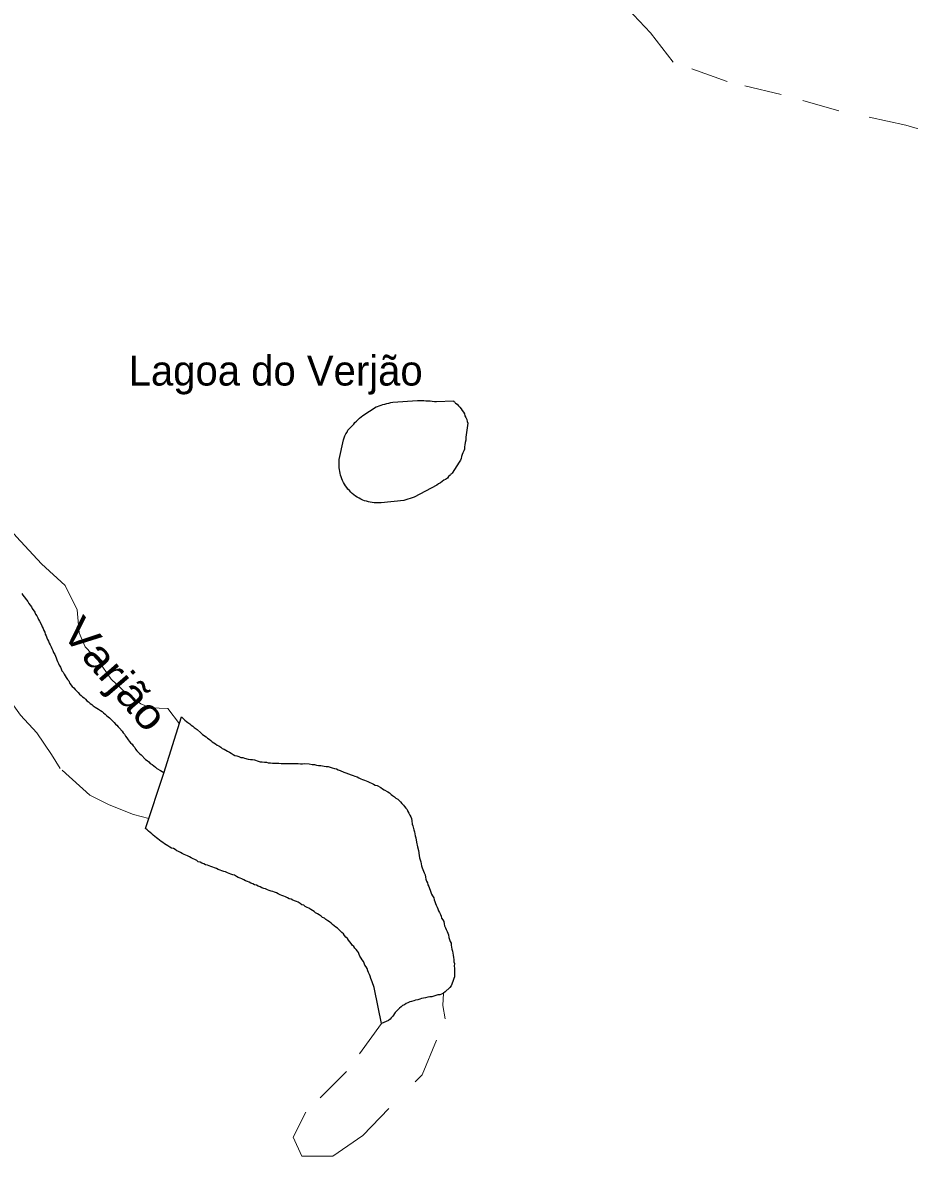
# Model space of a CAD drawing. Extents: x 785.9 to 812.4, y 7674.9 to 7703.1.
# Drawn here: x 791.218 to 793.585, y 7684.501 to 7687.529 of the extents above; entities that cross this region are included whole.
import ezdxf
from ezdxf.enums import TextEntityAlignment as Align

# ---------------------------------------------------------------- set-up
doc = ezdxf.new("R2010")
doc.units = 0
doc.header["$LTSCALE"] = 0.04
doc.linetypes.add('LONG_DASHED', pattern=[7.5, 6, -1.5])
doc.linetypes.add('SHORT_DASHED', pattern=[2.7, 1.5, -1.2])
for name, color, linetype, lineweight in [('2', 7, 'Continuous', 25), ('21', 7, 'SHORT_DASHED', 13), ('3', 7, 'LONG_DASHED', 25), ('7', 7, 'Continuous', 25)]:
    doc.layers.add(name, color=color, linetype=linetype, lineweight=lineweight)
doc.layers.add('61', color=7, linetype='Continuous')

msp = doc.modelspace()

# ---------------------------------------------------------------- linework, layer by layer
at = {"layer": '2'}
for points in [[(791.5945, 7685.5239), (791.5945, 7685.5239), (791.6422, 7685.6742)], [(791.6422, 7685.6742), (791.6439, 7685.6728), (791.6471, 7685.6688), (791.6512, 7685.6655), (791.6552, 7685.6623), (791.6592, 7685.6591), (791.6641, 7685.6558), (791.6681, 7685.6526), (791.6722, 7685.6494), (791.6762, 7685.6461), (791.6841, 7685.6408), (791.694, 7685.6315), (791.6981, 7685.6275), (791.7078, 7685.621)], [(791.7078, 7685.621), (791.7118, 7685.6178), (791.7159, 7685.6146), (791.7199, 7685.6113), (791.724, 7685.6081), (791.728, 7685.6048), (791.7329, 7685.6024), (791.7369, 7685.5992), (791.7418, 7685.5968), (791.7466, 7685.5935), (791.7507, 7685.5903), (791.7555, 7685.5879), (791.7604, 7685.5854), (791.7652, 7685.583), (791.7701, 7685.5798), (791.775, 7685.5773), (791.7798, 7685.5741), (791.7847, 7685.5717), (791.7895, 7685.5701), (791.7952, 7685.5684), (791.8, 7685.566), (791.8057, 7685.566), (791.8106, 7685.5644), (791.8203, 7685.5612), (791.8259, 7685.5603), (791.8316, 7685.5603), (791.8373, 7685.5595), (791.847, 7685.5563), (791.8518, 7685.5547), (791.8575, 7685.5547), (791.8632, 7685.5531), (791.8688, 7685.5531), (791.8737, 7685.5514), (791.8793, 7685.5514), (791.885, 7685.5506), (791.902, 7685.5506), (791.9077, 7685.5498), (791.9538, 7685.5498), (791.9594, 7685.549), (791.9651, 7685.549), (791.9708, 7685.5498), (791.9829, 7685.549), (791.991, 7685.5474), (791.9967, 7685.5474), (792.0023, 7685.5458), (792.008, 7685.545), (792.0137, 7685.5442), (792.0226, 7685.5425), (792.0282, 7685.5417), (792.0339, 7685.5417), (792.0387, 7685.5401), (792.0444, 7685.5385), (792.0509, 7685.5369), (792.0557, 7685.5353), (792.0606, 7685.5328), (792.0654, 7685.5312), (792.0751, 7685.5264), (792.0808, 7685.5247), (792.0954, 7685.5199), (792.1002, 7685.5175), (792.1051, 7685.5158), (792.1107, 7685.5142), (792.1156, 7685.5118), (792.1205, 7685.5086), (792.1253, 7685.5069), (792.1302, 7685.5053), (792.135, 7685.5037), (792.1399, 7685.5021), (792.1544, 7685.4948), (792.1593, 7685.4924), (792.1642, 7685.4908), (792.1739, 7685.4859), (792.1787, 7685.4827), (792.1828, 7685.4794), (792.1925, 7685.4746), (792.1973, 7685.4713), (792.2014, 7685.4673), (792.2054, 7685.4641), (792.2103, 7685.4608), (792.2143, 7685.4576), (792.2192, 7685.4543), (792.2232, 7685.4511), (792.2265, 7685.4471), (792.2305, 7685.443), (792.2345, 7685.439), (792.2378, 7685.4349), (792.241, 7685.4309), (792.2443, 7685.4268), (792.2467, 7685.422), (792.2491, 7685.4171), (792.2515, 7685.4123), (792.254, 7685.4074), (792.2564, 7685.4026), (792.2572, 7685.3969), (792.258, 7685.388), (792.2596, 7685.3831), (792.2621, 7685.3726), (792.2637, 7685.3678), (792.2653, 7685.3621), (792.2661, 7685.3564), (792.2677, 7685.3516)], [(791.546, 7685.3759), (791.5945, 7685.5239), (791.5945, 7685.5239)], [(791.7596, 7685.2602), (791.7547, 7685.2618), (791.7499, 7685.2634), (791.745, 7685.265), (791.7402, 7685.2666), (791.7353, 7685.2691), (791.7305, 7685.2715), (791.7256, 7685.2731), (791.7207, 7685.2747), (791.7159, 7685.2763), (791.711, 7685.278), (791.7062, 7685.2796), (791.7013, 7685.282), (791.6965, 7685.2836), (791.6916, 7685.286), (791.6868, 7685.2877), (791.6827, 7685.2909), (791.6779, 7685.2933), (791.673, 7685.2949), (791.6681, 7685.2982), (791.6633, 7685.3006), (791.6584, 7685.303), (791.6536, 7685.3055), (791.6487, 7685.3071), (791.6439, 7685.3095), (791.639, 7685.3119), (791.6342, 7685.3152), (791.6293, 7685.3168), (791.6253, 7685.32), (791.6204, 7685.3225), (791.6156, 7685.3241), (791.6107, 7685.3265), (791.6058, 7685.3297), (791.601, 7685.333), (791.5961, 7685.3354), (791.5921, 7685.3386), (791.5872, 7685.3419), (791.5832, 7685.3451), (791.5791, 7685.3483), (791.5751, 7685.3516), (791.5711, 7685.3548), (791.5662, 7685.3581), (791.563, 7685.3621), (791.5581, 7685.3653), (791.5541, 7685.3694), (791.55, 7685.3726), (791.546, 7685.3759)], [(792.2677, 7685.3516), (792.2693, 7685.3394), (792.2718, 7685.3273), (792.275, 7685.3176), (792.2766, 7685.3038), (792.2774, 7685.2982), (792.2791, 7685.2925), (792.2807, 7685.2869), (792.2823, 7685.282), (792.2831, 7685.2763), (792.2847, 7685.2715), (792.288, 7685.2626), (792.2896, 7685.2577), (792.2928, 7685.2529), (792.2936, 7685.2464), (792.2944, 7685.2407), (792.296, 7685.2359), (792.2985, 7685.231), (792.3001, 7685.2262), (792.3025, 7685.2213), (792.3041, 7685.2165), (792.3058, 7685.2116), (792.3074, 7685.2059), (792.3098, 7685.2011), (792.3122, 7685.1962), (792.3155, 7685.1914), (792.3163, 7685.1857), (792.3187, 7685.1809), (792.3203, 7685.176), (792.3219, 7685.1711), (792.3244, 7685.1663), (792.326, 7685.1614), (792.3284, 7685.1566), (792.3308, 7685.1517), (792.3333, 7685.1469), (792.3349, 7685.142), (792.3365, 7685.1372), (792.3397, 7685.1323), (792.3422, 7685.1275), (792.343, 7685.1218), (792.3446, 7685.1161), (792.347, 7685.1113), (792.3486, 7685.1064), (792.3511, 7685.1016), (792.3527, 7685.0967), (792.3551, 7685.0919), (792.3559, 7685.0854), (792.3575, 7685.0797), (792.3592, 7685.0749), (792.3616, 7685.07), (792.3616, 7685.0643), (792.3632, 7685.0595), (792.364, 7685.0538), (792.3656, 7685.049), (792.3664, 7685.0433), (792.3672, 7685.0376), (792.3681, 7685.032), (792.3689, 7685.0263), (792.3689, 7685.0206), (792.3705, 7685.0158), (792.3697, 7685.0085), (792.3713, 7685.0037), (792.3713, 7684.9859), (792.3705, 7684.9802), (792.3689, 7684.9753), (792.3672, 7684.9705), (792.364, 7684.9608), (792.3616, 7684.9559), (792.3583, 7684.9519), (792.3462, 7684.9397), (792.3414, 7684.9365), (792.3365, 7684.9341), (792.3316, 7684.9324), (792.326, 7684.9316), (792.3211, 7684.93), (792.3155, 7684.9284), (792.3106, 7684.9268), (792.3049, 7684.9268), (792.2993, 7684.926), (792.2936, 7684.9244), (792.288, 7684.9235), (792.2831, 7684.9219), (792.2782, 7684.9203), (792.2726, 7684.9187), (792.2669, 7684.9179), (792.2621, 7684.9163), (792.2564, 7684.9146), (792.2515, 7684.913), (792.2467, 7684.9106), (792.2418, 7684.909), (792.237, 7684.9057), (792.2321, 7684.9033), (792.2281, 7684.9001), (792.224, 7684.8968), (792.2159, 7684.8888), (792.2127, 7684.8847), (792.2062, 7684.875), (792.2022, 7684.871), (792.1989, 7684.8669), (792.1949, 7684.8637), (792.1763, 7684.8556)], [(792.1763, 7684.8556), (792.1577, 7684.947), (792.1561, 7684.9519), (792.1544, 7684.9567), (792.1528, 7684.9616), (792.1512, 7684.9664), (792.1496, 7684.9713), (792.1472, 7684.9761), (792.1455, 7684.9818), (792.1439, 7684.9867), (792.1415, 7684.9915), (792.1391, 7684.9964), (792.1375, 7685.002), (792.135, 7685.0069), (792.1318, 7685.0117), (792.1294, 7685.0166), (792.1277, 7685.0215), (792.1245, 7685.0255), (792.1213, 7685.0304), (792.118, 7685.0352), (792.1164, 7685.0401), (792.1148, 7685.0449), (792.1116, 7685.049), (792.1083, 7685.053), (792.1051, 7685.0571), (792.1018, 7685.0611), (792.0978, 7685.0651), (792.0946, 7685.0692), (792.0913, 7685.074), (792.0881, 7685.0781), (792.0849, 7685.0821), (792.0808, 7685.0862), (792.0776, 7685.0902), (792.0743, 7685.0951), (792.0703, 7685.0983), (792.0662, 7685.1024), (792.0622, 7685.1064), (792.0582, 7685.1097), (792.0541, 7685.1129), (792.0493, 7685.1161), (792.0452, 7685.1202), (792.0412, 7685.1234), (792.0371, 7685.1266), (792.0323, 7685.1299), (792.0274, 7685.1331), (792.0234, 7685.1364), (792.0185, 7685.1388), (792.0145, 7685.142), (792.0096, 7685.1453), (792.0048, 7685.1485), (791.9999, 7685.1509), (791.9959, 7685.1542), (791.9918, 7685.1574), (791.987, 7685.1598), (791.9821, 7685.1631), (791.9772, 7685.1655), (791.9724, 7685.1679), (791.9683, 7685.1711), (791.9635, 7685.1728), (791.9586, 7685.176), (791.9538, 7685.1792), (791.9489, 7685.1809), (791.9441, 7685.1833), (791.9392, 7685.1849), (791.9344, 7685.1873), (791.9295, 7685.1889), (791.9246, 7685.1914), (791.9198, 7685.1938), (791.9149, 7685.1954), (791.9101, 7685.1978), (791.9052, 7685.1995), (791.9004, 7685.2019), (791.8955, 7685.2043), (791.8907, 7685.2059), (791.8858, 7685.2076), (791.881, 7685.2092), (791.8761, 7685.2108), (791.8712, 7685.2124), (791.8664, 7685.2148), (791.8615, 7685.2165), (791.8567, 7685.2181), (791.8518, 7685.2205), (791.847, 7685.2221), (791.8421, 7685.2246), (791.8373, 7685.2262), (791.8324, 7685.2286), (791.8275, 7685.2302), (791.8227, 7685.2326), (791.8178, 7685.2351), (791.813, 7685.2367), (791.8081, 7685.2391), (791.8033, 7685.2415), (791.7984, 7685.244), (791.7936, 7685.2456), (791.7887, 7685.248), (791.7839, 7685.2513), (791.779, 7685.2529), (791.7741, 7685.2545), (791.7693, 7685.2561), (791.7644, 7685.2577), (791.7596, 7685.2602)]]:
    msp.add_lwpolyline(points, dxfattribs=at)
at = {"layer": '21'}
for points in [[(793.6703, 7687.2275), (793.576, 7687.2548), (793.397, 7687.2933), (793.2432, 7687.3366), (793.0987, 7687.3718), (792.9549, 7687.4236), (792.8941, 7687.5014), (792.834, 7687.5659)], [(791.5548, 7685.4027), (791.5139, 7685.4139), (791.4488, 7685.4396), (791.397, 7685.465), (791.3183, 7685.5366), (791.2948, 7685.574), (791.2556, 7685.6319), (791.212, 7685.6791), (791.1291, 7685.794), (791.1138, 7685.8382), (791.0887, 7685.9067), (791.0547, 7685.9514), (791.0527, 7686.0036), (790.9867, 7686.1088), (790.9293, 7686.1623), (790.874, 7686.207), (790.7932, 7686.2644), (790.621, 7686.3261), (790.6043, 7686.3329)], [(791.023, 7686.3275), (791.0544, 7686.3064), (791.0817, 7686.2797), (791.1387, 7686.2265), (791.2014, 7686.1556), (791.2682, 7686.083), (791.331, 7686.0251), (791.3636, 7685.9607), (791.3689, 7685.8993), (791.3844, 7685.8618), (791.4195, 7685.8251), (791.4545, 7685.7754), (791.4953, 7685.7371), (791.5336, 7685.7094), (791.5588, 7685.6988), (791.6053, 7685.6971), (791.6364, 7685.6559)], [(792.1763, 7684.8556), (792.0826, 7684.7274), (791.974, 7684.6187), (791.9405, 7684.5517), (791.9633, 7684.5007), (792.0463, 7684.5014), (792.1259, 7684.5566), (792.2843, 7684.7188), (792.3462, 7684.8677), (792.3394, 7684.9035), (792.3419, 7684.9368)]]:
    msp.add_lwpolyline(points, dxfattribs=at)
at = {"layer": '3'}
for points in [[(792.0722, 7686.3056), (792.0702, 7686.3104), (792.0684, 7686.3153), (792.0669, 7686.3202), (792.0656, 7686.3251), (792.0647, 7686.3299), (792.0639, 7686.3348), (792.0634, 7686.3395), (792.0631, 7686.3442), (792.063, 7686.3452), (792.063, 7686.3509), (792.063, 7686.3565), (792.063, 7686.3622), (792.0742, 7686.4144), (792.0743, 7686.4148), (792.0784, 7686.4253), (792.0808, 7686.4302), (792.084, 7686.435), (792.0865, 7686.4399), (792.0897, 7686.4439), (792.0938, 7686.448), (792.0978, 7686.452), (792.1018, 7686.4561), (792.1051, 7686.4609), (792.1091, 7686.4642), (792.1132, 7686.4682), (792.1172, 7686.4722), (792.1221, 7686.4755), (792.1261, 7686.4795), (792.1617, 7686.503), (792.165, 7686.5038), (792.1698, 7686.5054), (792.1747, 7686.507), (792.1795, 7686.5087), (792.1852, 7686.5095), (792.19, 7686.5111), (792.1957, 7686.5127), (792.2006, 7686.5143), (792.2062, 7686.5151), (792.2718, 7686.5192), (792.2774, 7686.5192), (792.2831, 7686.5192), (792.2888, 7686.5192), (792.2944, 7686.5184), (792.3001, 7686.5184), (792.3058, 7686.5184), (792.3114, 7686.5176), (792.3171, 7686.5168), (792.3227, 7686.5168), (792.368, 7686.5184), (792.3683, 7686.5181), (792.3695, 7686.5169), (792.3706, 7686.5158), (792.3718, 7686.5147), (792.3729, 7686.5135), (792.3737, 7686.5127), (792.3778, 7686.5095), (792.3818, 7686.5054), (792.385, 7686.5014), (792.3883, 7686.4973), (792.3915, 7686.4925), (792.3948, 7686.4884), (792.3972, 7686.4836), (792.3988, 7686.4787), (792.4012, 7686.4739), (792.4037, 7686.469), (792.4045, 7686.4633), (792.4061, 7686.4585), (792.4012, 7686.4213), (792.4012, 7686.4205), (792.4012, 7686.4188), (792.4012, 7686.4172), (792.4012, 7686.4156), (792.4012, 7686.414), (792.4012, 7686.4132), (792.3996, 7686.4075), (792.3988, 7686.401), (792.398, 7686.3954), (792.3972, 7686.3897), (792.3956, 7686.3849), (792.3931, 7686.38), (792.3915, 7686.3752), (792.3899, 7686.3695), (792.3883, 7686.3646), (792.3867, 7686.3598), (792.3834, 7686.3549), (792.3643, 7686.3253), (792.3637, 7686.3247), (792.3626, 7686.3236), (792.3614, 7686.3224), (792.3603, 7686.3213), (792.3592, 7686.3201), (792.3551, 7686.3161), (792.3519, 7686.312), (792.347, 7686.3088), (792.3422, 7686.3064), (792.3381, 7686.3031), (792.3333, 7686.2999), (792.3284, 7686.2967), (792.3236, 7686.2934), (792.263, 7686.2611)], [(792.263, 7686.2611), (792.2354, 7686.2522), (792.1755, 7686.2465), (792.1708, 7686.2461), (792.166, 7686.246), (792.1611, 7686.246), (792.1562, 7686.2463), (792.1512, 7686.2469), (792.1512, 7686.2469), (792.1461, 7686.2477), (792.1411, 7686.2488), (792.136, 7686.2502), (792.1309, 7686.2518), (792.1259, 7686.2537), (792.121, 7686.2559), (792.1161, 7686.2584), (792.1114, 7686.2612), (792.1068, 7686.2642), (792.1024, 7686.2675), (792.0981, 7686.271), (792.094, 7686.2747), (792.0902, 7686.2787), (792.0865, 7686.2828), (792.0832, 7686.2871), (792.08, 7686.2916), (792.0772, 7686.2961), (792.0746, 7686.3008), (792.0722, 7686.3056)]]:
    msp.add_lwpolyline(points, dxfattribs=at)
at = {"layer": '7'}
msp.add_line((791.5899, 7685.5284), (791.5951, 7685.5257), dxfattribs=at)
for points in [[(791.2152, 7686.0041), (791.2185, 7685.9993), (791.2217, 7685.9952), (791.2282, 7685.9871), (791.2314, 7685.9823), (791.2346, 7685.9774), (791.2379, 7685.9726)], [(791.2379, 7685.9726), (791.2411, 7685.9685), (791.2435, 7685.9637), (791.25, 7685.954), (791.2524, 7685.9491), (791.2557, 7685.9443), (791.2581, 7685.9394), (791.2605, 7685.9346), (791.263, 7685.9297), (791.2678, 7685.92), (791.2702, 7685.9151), (791.2727, 7685.9103), (791.2743, 7685.9054), (791.2767, 7685.9006), (791.2783, 7685.8957), (791.2808, 7685.8909), (791.2824, 7685.886), (791.284, 7685.8811), (791.2864, 7685.8763), (791.2889, 7685.8714), (791.2913, 7685.8666), (791.2937, 7685.8617), (791.2961, 7685.8569), (791.2986, 7685.852), (791.3002, 7685.8464), (791.3034, 7685.8415), (791.3059, 7685.8366), (791.3075, 7685.8318), (791.3091, 7685.8269), (791.3107, 7685.8221), (791.3131, 7685.8172), (791.3156, 7685.8124), (791.3188, 7685.8075), (791.3204, 7685.8027), (791.3228, 7685.7978), (791.3261, 7685.7938), (791.3285, 7685.7889), (791.3317, 7685.784), (791.3342, 7685.7792), (791.3374, 7685.7743), (791.3415, 7685.7703), (791.3439, 7685.7638), (791.3504, 7685.7557), (791.3544, 7685.7517), (791.3576, 7685.7476), (791.3657, 7685.7395), (791.3698, 7685.7355), (791.3738, 7685.7315), (791.3779, 7685.7282), (791.3819, 7685.725), (791.386, 7685.7217), (791.3892, 7685.7177), (791.394, 7685.7145), (791.3981, 7685.7104), (791.4021, 7685.7072), (791.4062, 7685.7039), (791.411, 7685.7007), (791.4159, 7685.6975), (791.4207, 7685.695), (791.4256, 7685.6918), (791.4297, 7685.6886), (791.4337, 7685.6853), (791.4377, 7685.6813), (791.4418, 7685.6781), (791.4458, 7685.6748), (791.4499, 7685.6716), (791.462, 7685.6594), (791.4653, 7685.6554), (791.4693, 7685.6522), (791.4725, 7685.6481), (791.4766, 7685.6441), (791.4831, 7685.636), (791.4863, 7685.6319), (791.4895, 7685.6279), (791.4928, 7685.623), (791.496, 7685.6182), (791.4992, 7685.6133), (791.5025, 7685.6093), (791.5057, 7685.6052), (791.5098, 7685.6012), (791.513, 7685.5971), (791.517, 7685.5931), (791.5195, 7685.5882), (791.5227, 7685.5842), (791.5259, 7685.5801), (791.53, 7685.5769), (791.534, 7685.5729), (791.5462, 7685.5607), (791.5502, 7685.5575), (791.5543, 7685.5543), (791.5583, 7685.5502), (791.5632, 7685.547), (791.568, 7685.5437), (791.5721, 7685.5405), (791.5761, 7685.5365), (791.5858, 7685.5316), (791.5899, 7685.5284)]]:
    msp.add_lwpolyline(points, dxfattribs=at)

# ---------------------------------------------------------------- texts
at = {"layer": '61'}
msp.add_text('Lagoa do Verjão', height=0.08, dxfattribs=at).set_placement((791.5008, 7686.5594))
at = {"layer": '61', "width": 1.15}
msp.add_text('Varjão', height=0.08, rotation=310.705, dxfattribs=at).set_placement((791.4342, 7685.763), align=Align.CENTER)

doc.saveas('drawing.dxf')
